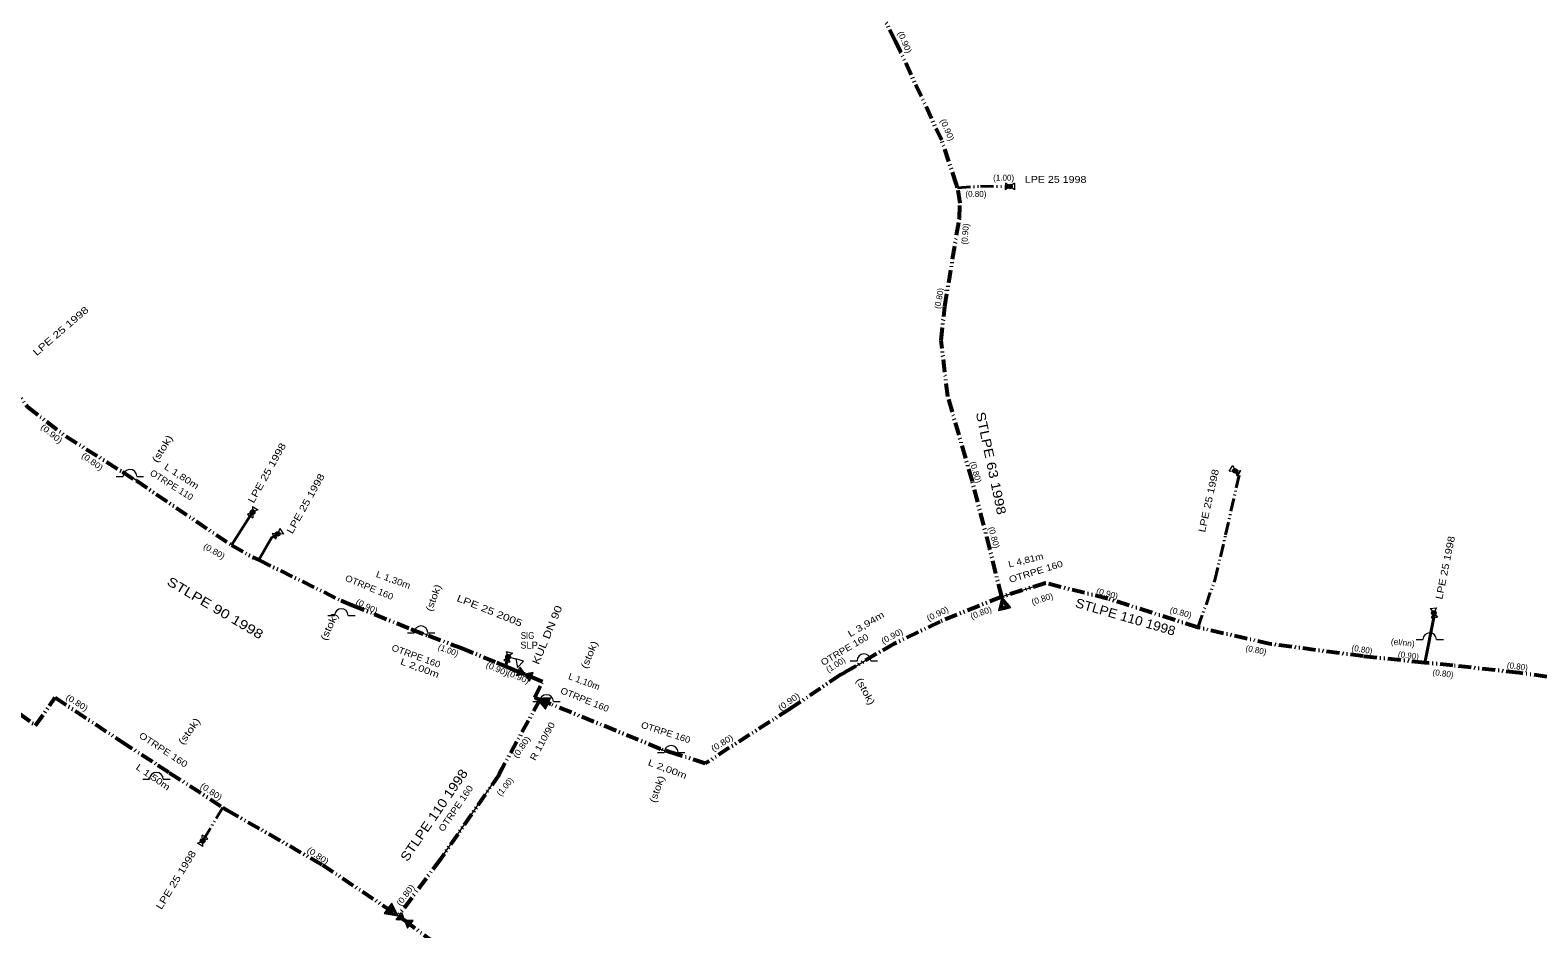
# Model space of a CAD drawing. Extents: x -648036 to -642998, y -1161549 to -1158141.
# Drawn here: x -644334.7 to -644171.4, y -1160292.8 to -1160195.5 of the extents above; entities that cross this region are included whole.
import ezdxf
from ezdxf.enums import TextEntityAlignment as Align

# ---------------------------------------------------------------- set-up
doc = ezdxf.new("R2010")
doc.units = 0
doc.header["$LTSCALE"] = 0.28
doc.linetypes.add('DASH_DOUBLE_DOT', pattern=[9.2, 5, -1.2, 0.3, -1.2, 0.3, -1.2])
for name, color, linetype, lineweight in [('12', 7, 'DASH_DOUBLE_DOT', 40), ('14', 7, 'Continuous', 13), ('15', 7, 'Continuous', 13), ('19', 7, 'Continuous', 13), ('8', 7, 'Continuous', 53)]:
    doc.layers.add(name, color=color, linetype=linetype, lineweight=lineweight)
for name, color, linetype in [('20', 7, 'Continuous'), ('22', 7, 'Continuous'), ('24', 7, 'Continuous'), ('25', 7, 'Continuous'), ('27', 7, 'Continuous'), ('28', 7, 'Continuous'), ('35', 7, 'Continuous')]:
    doc.layers.add(name, color=color, linetype=linetype)

msp = doc.modelspace()

# ---------------------------------------------------------------- linework, layer by layer
at = {"layer": '12', "linetype": 'Continuous'}
msp.add_line((-644312.85, -1160251.24), (-644310.56, -1160247.66), dxfattribs=at)
at = {"layer": '12'}
msp.add_line((-644313.77, -1160279.64), (-644315.98, -1160283.27), dxfattribs=at)
for points in [[(-644234.2, -1160212.56), (-644231.71, -1160212.39), (-644228.53, -1160212.41)], [(-644208.17, -1160260.16), (-644206.35, -1160255.03), (-644205.17, -1160250.11), (-644203.67, -1160243.51), (-644204.16, -1160243.2)]]:
    msp.add_lwpolyline(points, dxfattribs=at)
at = {"layer": '12', "linetype": 'Continuous'}
for points in [[(-644309.88, -1160252.85), (-644308.53, -1160250.45), (-644307.84, -1160250.02)], [(-644183.61, -1160263.97), (-644182.58, -1160258.91), (-644182.62, -1160258.57)], [(-644283.18, -1160264.35), (-644283.15, -1160264.25), (-644282.89, -1160263.33)]]:
    msp.add_lwpolyline(points, dxfattribs=at)
at = {"layer": '14'}
for p, q in [((-644323.15, -1160244.26), (-644324.67, -1160243.3)), ((-644224.69, -1160255.36), (-644229.29, -1160256.79)), ((-644299.78, -1160257.73), (-644300.98, -1160257.24)), ((-644291.52, -1160261.04), (-644293.39, -1160260.34)), ((-644246.47, -1160265.05), (-644242.97, -1160263.02)), ((-644278.25, -1160268.47), (-644279.27, -1160268.06)), ((-644266.37, -1160273.32), (-644264.47, -1160273.93)), ((-644319.55, -1160275.89), (-644320.81, -1160275.07))]:
    msp.add_line(p, q, dxfattribs=at)
msp.add_lwpolyline([(-644290.21, -1160285.23), (-644283.87, -1160276.09), (-644283.57, -1160275.45)], dxfattribs=at)
at = {"layer": '15'}
for p, q in [((-644229.031, -1160212.051), (-644229.036, -1160212.763)), ((-644228.024, -1160212.057), (-644229.036, -1160212.763)), ((-644228.028, -1160212.769), (-644229.031, -1160212.051)), ((-644228.024, -1160212.057), (-644228.028, -1160212.769)), ((-644204.776, -1160243.231), (-644204.396, -1160242.63)), ((-644204.776, -1160243.231), (-644203.544, -1160243.169)), ((-644204.396, -1160242.63), (-644203.925, -1160243.77)), ((-644203.925, -1160243.77), (-644203.544, -1160243.169)), ((-644325.325, -1160243.795), (-644324.59, -1160243.794)), ((-644323.104, -1160243.794), (-644322.37, -1160243.795)), ((-644309.989, -1160247.427), (-644311.131, -1160247.892)), ((-644311.131, -1160247.892), (-644310.532, -1160248.276)), ((-644310.588, -1160247.044), (-644310.532, -1160248.276)), ((-644310.588, -1160247.044), (-644309.989, -1160247.427)), ((-644308.455, -1160249.984), (-644308.079, -1160250.589)), ((-644307.224, -1160250.056), (-644308.455, -1160249.984)), ((-644307.601, -1160249.451), (-644308.079, -1160250.589)), ((-644307.601, -1160249.451), (-644307.224, -1160250.056)), ((-644183.032, -1160258.111), (-644182.325, -1160258.028)), ((-644183.032, -1160258.111), (-644182.208, -1160259.029)), ((-644182.325, -1160258.028), (-644182.915, -1160259.111)), ((-644302.425, -1160258.865), (-644301.69, -1160258.864)), ((-644300.204, -1160258.864), (-644299.47, -1160258.865)), ((-644182.915, -1160259.111), (-644182.208, -1160259.029)), ((-644293.795, -1160260.735), (-644293.06, -1160260.734)), ((-644291.574, -1160260.734), (-644290.84, -1160260.735)), ((-644184.545, -1160261.475), (-644183.81, -1160261.474)), ((-644182.324, -1160261.474), (-644181.59, -1160261.475)), ((-644282.41, -1160262.942), (-644283.369, -1160263.717)), ((-644283.096, -1160262.748), (-644282.684, -1160263.912)), ((-644283.096, -1160262.748), (-644282.41, -1160262.942)), ((-644282.89, -1160263.33), (-644282.065, -1160263.563)), ((-644283.369, -1160263.717), (-644282.684, -1160263.912)), ((-644281.51, -1160264.583), (-644281.83, -1160265.357)), ((-644281.418, -1160264.72), (-644281.667, -1160265.325)), ((-644281.339, -1160264.838), (-644281.529, -1160265.297)), ((-644281.271, -1160264.939), (-644281.408, -1160265.273)), ((-644245.825, -1160263.755), (-644245.09, -1160263.754)), ((-644243.604, -1160263.754), (-644242.87, -1160263.755)), ((-644281.182, -1160265.071), (-644281.254, -1160265.242)), ((-644280.937, -1160265.179), (-644281.003, -1160265.339)), ((-644280.776, -1160265.147), (-644280.911, -1160265.476)), ((-644280.615, -1160265.116), (-644280.821, -1160265.611)), ((-644280.47, -1160265.087), (-644280.738, -1160265.735)), ((-644280.314, -1160265.056), (-644280.649, -1160265.866)), ((-644280.205, -1160268.175), (-644279.47, -1160268.174)), ((-644277.984, -1160268.174), (-644277.25, -1160268.175)), ((-644266.705, -1160273.685), (-644265.97, -1160273.684)), ((-644264.484, -1160273.684), (-644263.75, -1160273.685)), ((-644322.455, -1160276.595), (-644321.72, -1160276.594)), ((-644320.234, -1160276.594), (-644319.5, -1160276.595)), ((-644315.414, -1160283.025), (-644316.022, -1160282.654)), ((-644315.938, -1160283.886), (-644316.022, -1160282.654)), ((-644316.546, -1160283.515), (-644315.414, -1160283.025)), ((-644315.938, -1160283.886), (-644316.546, -1160283.515)), ((-644294.365, -1160291.153), (-644294.854, -1160291.833)), ((-644294.306, -1160291.308), (-644294.688, -1160291.839)), ((-644294.256, -1160291.441), (-644294.547, -1160291.844)), ((-644294.214, -1160291.555), (-644294.424, -1160291.848)), ((-644294.158, -1160291.704), (-644294.267, -1160291.853)), ((-644293.944, -1160291.865), (-644294.045, -1160292.006)), ((-644293.78, -1160291.871), (-644293.987, -1160292.16)), ((-644293.616, -1160291.877), (-644293.931, -1160292.312)), ((-644293.468, -1160291.883), (-644293.878, -1160292.452)), ((-644293.31, -1160291.889), (-644293.822, -1160292.6))]:
    msp.add_line(p, q, dxfattribs=at)
for points in [[(-644228.435, -1160258.007), (-644229.43, -1160256.83), (-644229.769, -1160258.334), (-644229.101, -1160258.17)], [(-644228.615, -1160257.948), (-644229.376, -1160257.049), (-644229.635, -1160258.198)], [(-644228.797, -1160257.89), (-644229.324, -1160257.266), (-644229.503, -1160258.063)], [(-644228.978, -1160257.831), (-644229.27, -1160257.485), (-644229.369, -1160257.927)], [(-644282.065, -1160263.563), (-644281.88, -1160264.506), (-644281.228, -1160263.8)], [(-644281.09, -1160265.21), (-644281.992, -1160265.389), (-644281.601, -1160264.447), (-644280.578, -1160265.974), (-644280.188, -1160265.031)], [(-644278.28, -1160267.764), (-644279.82, -1160267.83), (-644278.838, -1160269.018), (-644278.559, -1160268.39)], [(-644278.437, -1160267.87), (-644279.614, -1160267.921), (-644278.864, -1160268.83)], [(-644278.595, -1160267.978), (-644279.41, -1160268.013), (-644278.89, -1160268.642)], [(-644278.751, -1160268.085), (-644279.204, -1160268.105), (-644278.915, -1160268.453)], [(-644296.301, -1160291.12), (-644294.78, -1160291.37), (-644295.498, -1160290.006), (-644295.9, -1160290.563)], [(-644296.125, -1160291.048), (-644294.963, -1160291.238), (-644295.512, -1160290.196)], [(-644295.949, -1160290.974), (-644295.144, -1160291.107), (-644295.525, -1160290.385)], [(-644295.774, -1160290.902), (-644295.326, -1160290.975), (-644295.538, -1160290.575)], [(-644294.1, -1160291.86), (-644295.019, -1160291.827), (-644294.422, -1160291), (-644293.778, -1160292.721), (-644293.181, -1160291.893)]]:
    msp.add_lwpolyline(points, close=True, dxfattribs=at)
for centre in [(-644323.8474, -1160243.7946), (-644300.9474, -1160258.8646), (-644292.3174, -1160260.7346), (-644183.0674, -1160261.4746), (-644244.3474, -1160263.7546), (-644278.7274, -1160268.1746), (-644265.2274, -1160273.6846), (-644320.9774, -1160276.5946)]:
    msp.add_arc(centre, 0.7431, 1.2748, 179.83951, dxfattribs=at)
at = {"layer": '19'}
for centre, radius in [((-644228.53, -1160212.41), 0.25), ((-644228.53, -1160212.41), 0.17), ((-644228.53, -1160212.41), 0.09), ((-644204.16, -1160243.2), 0.25), ((-644204.16, -1160243.2), 0.17), ((-644204.16, -1160243.2), 0.09), ((-644310.56, -1160247.66), 0.25), ((-644310.56, -1160247.66), 0.17), ((-644310.56, -1160247.66), 0.09), ((-644307.84, -1160250.02), 0.25), ((-644307.84, -1160250.02), 0.17), ((-644307.84, -1160250.02), 0.09), ((-644182.62, -1160258.57), 0.25), ((-644182.62, -1160258.57), 0.17), ((-644182.62, -1160258.57), 0.09), ((-644282.89, -1160263.33), 0.25), ((-644282.89, -1160263.33), 0.17), ((-644282.89, -1160263.33), 0.09), ((-644315.98, -1160283.27), 0.25), ((-644315.98, -1160283.27), 0.17), ((-644315.98, -1160283.27), 0.09)]:
    msp.add_circle(centre, radius, dxfattribs=at)
at = {"layer": '8', "linetype": 'DASH_DOUBLE_DOT'}
for p, q in [((-644282.25, -1160264.73), (-644281.09, -1160265.21)), ((-644279.45, -1160267.98), (-644279.82, -1160267.83)), ((-644294.78, -1160291.37), (-644294.1, -1160291.86))]:
    msp.add_line(p, q, dxfattribs=at)
for points in [[(-644234.2, -1160212.56), (-644234.31, -1160212.18), (-644235.92, -1160207.4), (-644240.39, -1160197.82), (-644240.92, -1160196.71), (-644243.57, -1160191.37)], [(-644229.43, -1160256.83), (-644230.7, -1160251.65), (-644232.6, -1160244.35), (-644235.27, -1160235.12), (-644235.98, -1160229.07), (-644235.6, -1160225.41), (-644234, -1160215.86), (-644233.94, -1160214.2), (-644234.2, -1160212.56)], [(-644338.29, -1160231.89), (-644334.94, -1160236.28), (-644330.79, -1160239.46), (-644324.67, -1160243.3), (-644323.15, -1160244.26), (-644312.85, -1160251.24)], [(-644312.85, -1160251.24), (-644310.47, -1160252.59), (-644309.88, -1160252.85)], [(-644309.88, -1160252.85), (-644300.98, -1160257.24), (-644299.78, -1160257.73), (-644293.39, -1160260.34), (-644291.52, -1160261.04), (-644287.98, -1160262.36), (-644284.1, -1160263.96)], [(-644353.99, -1160256.04), (-644352.87, -1160256.88), (-644344.28, -1160263.37), (-644334.06, -1160270.77), (-644331.94, -1160267.75), (-644324.78, -1160272.5), (-644320.81, -1160275.07), (-644319.55, -1160275.89), (-644313.77, -1160279.64)], [(-644208.17, -1160260.16), (-644217.92, -1160257.05), (-644224.69, -1160255.36), (-644229.29, -1160256.79), (-644229.43, -1160256.83)], [(-644229.43, -1160256.83), (-644236.14, -1160259.53), (-644241.09, -1160261.94), (-644242.97, -1160263.02), (-644246.47, -1160265.05), (-644246.9, -1160265.3), (-644252.35, -1160268.97), (-644261.53, -1160274.88), (-644264.47, -1160273.93), (-644266.37, -1160273.32), (-644278.25, -1160268.47), (-644279.27, -1160268.06), (-644279.45, -1160267.98)], [(-644183.61, -1160263.97), (-644190.26, -1160263.28), (-644200.31, -1160261.95), (-644208.17, -1160260.16)], [(-644158.61, -1160267.34), (-644162.84, -1160266.58), (-644167.8, -1160265.86), (-644173.39, -1160265.07), (-644180.55, -1160264.28), (-644183.61, -1160263.97)], [(-644279.82, -1160267.83), (-644280, -1160267.75), (-644279.18, -1160266.05), (-644281.09, -1160265.21)], [(-644279.45, -1160267.98), (-644283.57, -1160275.45), (-644283.87, -1160276.09), (-644290.21, -1160285.23), (-644294.78, -1160291.37)], [(-644313.77, -1160279.64), (-644313.33, -1160279.92), (-644303, -1160285.85), (-644294.78, -1160291.37)], [(-644294.1, -1160291.86), (-644290.54, -1160294.56), (-644289.87, -1160295.05), (-644284.97, -1160298.33)]]:
    msp.add_lwpolyline(points, dxfattribs=at)
at = {"layer": '8'}
msp.add_lwpolyline([(-644284.1, -1160263.96), (-644283.18, -1160264.35), (-644282.25, -1160264.73)], dxfattribs=at)

# ---------------------------------------------------------------- texts
at = {"layer": '15'}
msp.add_text('SLP', height=0.75, dxfattribs=at).set_placement((-644280.614, -1160262.446), align=Align.CENTER)
at = {"layer": '15', "width": 0.85}
msp.add_text('SIG', height=0.75, dxfattribs=at).set_placement((-644280.7835, -1160261.402), align=Align.CENTER)
at = {"layer": '20'}
for s, rotation, width, p in [('STLPE 63 1998', 281.895, 1.2, (-644231.0669, -1160242.4734)), ('STLPE 90 1998', 329.451, 1.25, (-644314.8641, -1160258.4683)), ('STLPE 110 1998', 343.775, 1.1, (-644216.1592, -1160259.4913)), ('STLPE 110 1998', 55.577, 1.15, (-644290.4995, -1160280.7582))]:
    msp.add_text(s, height=1, rotation=rotation, dxfattribs=dict(at, width=width)).set_placement(p, align=Align.CENTER)
at = {"layer": '22'}
for s, rotation, width, p in [('LPE 25 1998', 359.818, 1.15, (-644223.5897, -1160212.0188)), ('LPE 25 1998', 40.68, 1.3, (-644331.1009, -1160228.3422)), ('LPE 25 1998', 60.734, 1.25, (-644308.679, -1160243.6073)), ('LPE 25 1998', 60.734, 1.25, (-644304.489, -1160246.9273)), ('LPE 25 1998', 77.349, 1.2, (-644206.6494, -1160246.5116)), ('LPE 25 1998', 78.495, 1.2, (-644181.017, -1160253.7593)), ('LPE 25 2005', 338.045, 1.3, (-644285.0292, -1160258.6775)), ('LPE 25 1998', 58.442, 1.25, (-644318.5421, -1160287.6793))]:
    msp.add_text(s, height=0.75, rotation=rotation, dxfattribs=dict(at, width=width)).set_placement(p, align=Align.CENTER)
at = {"layer": '24'}
for s, rotation, width, p in [('OTRPE 110', 327.732, 1.05, (-644319.5129, -1160245.0198)), ('L 1,80m', 327.159, 1.25, (-644318.4393, -1160244.0803)), ('L 4,81m', 13.751, 1.15, (-644226.7357, -1160253.2058)), ('OTRPE 160 ', 17.189, 1.2, (-644225.4719, -1160254.3928)), ('OTRPE 160', 337.472, 1.1, (-644298.0536, -1160256.1364)), ('L 1,30m', 339.764, 1.15, (-644295.4371, -1160255.3289)), ('L 3,94m', 30.94, 1.3, (-644243.9494, -1160260.1012)), ('OTRPE 160', 30.367, 1.15, (-644246.2589, -1160262.8581)), ('OTRPE 160', 339.764, 1.1, (-644292.9786, -1160263.5821)), ('L 2,00m', 339.764, 1.3, (-644292.5656, -1160264.8759)), ('L 1,10m', 339.764, 1.05, (-644274.7681, -1160266.3343)), ('OTRPE 160', 338.045, 1.1, (-644274.7164, -1160268.295)), ('OTRPE 160', 342.056, 1.1, (-644265.9148, -1160271.8486)), ('OTRPE 160 ', 326.586, 1.2, (-644320.2897, -1160273.7761)), ('L 2,00m', 339.764, 1.3, (-644265.7456, -1160275.8159)), ('L 1,50m', 325.44, 1.25, (-644321.5375, -1160276.64)), ('OTRPE 160', 55.577, 1.15, (-644288.2669, -1160279.9424))]:
    msp.add_text(s, height=0.7, rotation=rotation, dxfattribs=dict(at, width=width)).set_placement(p, align=Align.CENTER)
at = {"layer": '25', "width": 1.2}
msp.add_text('R 110/90', height=0.7, rotation=61.306, dxfattribs=at).set_placement((-644278.865, -1160272.638), align=Align.CENTER)
at = {"layer": '27'}
for s, rotation, width, p in [('(0.90)', 293.354, 1.1, (-644240.216, -1160196.9127)), ('(0.90)', 293.354, 1.1, (-644235.616, -1160206.4027)), ('(0.90)', 320.283, 1.2, (-644332.5427, -1160239.4256)), ('(0.80)', 323.721, 1.15, (-644328.1058, -1160242.4493)), ('(0.80)', 286.479, 1.05, (-644232.547, -1160243.4348)), ('(0.80)', 285.333, 1.05, (-644230.5687, -1160250.5086)), ('(0.80)', 330.597, 1.1, (-644314.8771, -1160252.1801)), ('(0.80)', 17.189, 1.05, (-644224.94, -1160257.3661)), ('(0.90)', 344.921, 1.05, (-644218.0871, -1160256.7856)), ('(0.90)', 333.461, 1.1, (-644298.3382, -1160258.1456)), ('(0.90)', 25.783, 1.1, (-644236.2324, -1160258.967)), ('(0.80)', 20.626, 1.05, (-644231.56, -1160258.86)), ('(0.80)', 344.921, 1.05, (-644210.1131, -1160258.841)), ('(0.90)', 28.075, 1.1, (-644241.159, -1160261.3775)), ('(el/nn)', 353.515, 1.05, (-644186.0172, -1160262.1125)), ('(0.90)', 336.326, 1.1, (-644284.2155, -1160264.9353)), ('(0.90)', 337.472, 1.1, (-644281.9025, -1160265.8016)), ('(0.80)', 328.305, 1.15, (-644329.7533, -1160268.5714)), ('(0.90)', 34.95, 1.15, (-644252.2992, -1160268.4497)), ('(0.80)', 56.15, 1.15, (-644281.1663, -1160273.28)), ('(0.80)', 31.513, 1.15, (-644259.5439, -1160272.9394)), ('(0.80)', 326.013, 1.15, (-644315.2197, -1160278.184)), ('(0.80)', 326.013, 1.15, (-644303.6697, -1160285.134)), ('(0.80)', 53.285, 1.15, (-644293.7577, -1160289.3133))]:
    msp.add_text(s, height=0.65, rotation=rotation, dxfattribs=dict(at, width=width)).set_placement(p, align=Align.CENTER)
for s, p in [('(1.00)', (-644229.2205, -1160211.79)), ('(0.80)', (-644232.22, -1160213.54))]:
    msp.add_text(s, height=0.65, dxfattribs=at).set_placement(p, align=Align.CENTER)
for s, rotation, p in [('(0.90)', 85.371, (-644233.0667, -1160217.5772)), ('(0.80)', 79.641, (-644235.8916, -1160224.5819)), ('(1.00)', 339.191, (-644289.48, -1160262.9251)), ('(0.80)', 348.931, (-644201.9379, -1160262.9088)), ('(0.80)', 350.077, (-644190.454, -1160262.8489)), ('(0.90)', 351.796, (-644185.4174, -1160263.5016)), ('(1.00)', 32.086, (-644247.2386, -1160264.4705)), ('(0.80)', 351.796, (-644181.6639, -1160265.4492)), ('(0.80)', 351.796, (-644173.6139, -1160264.6892)), ('(1.00)', 50.993, (-644282.9692, -1160277.5946))]:
    msp.add_text(s, height=0.65, rotation=rotation, dxfattribs=at).set_placement(p, align=Align.CENTER)
at = {"layer": '28'}
for rotation, width, p in [(57.869, 1.3, (-644320.0297, -1160241.0014)), (69.328, 1.2, (-644290.6295, -1160257.0749)), (64.744, 1.25, (-644301.9238, -1160260.2225)), (67.036, 1.25, (-644273.7434, -1160263.2543)), (297.938, 1.25, (-644244.5011, -1160267.2408)), (54.431, 1.3, (-644317.1323, -1160271.6066)), (70.474, 1.2, (-644266.4193, -1160277.7828))]:
    msp.add_text('(stok)', height=0.75, rotation=rotation, dxfattribs=dict(at, width=width)).set_placement(p, align=Align.CENTER)
at = {"layer": '35', "width": 1.25}
msp.add_text('KUL DN 90', height=0.8, rotation=67.609, dxfattribs=at).set_placement((-644278.2848, -1160261.1134), align=Align.CENTER)

doc.saveas('drawing.dxf')
